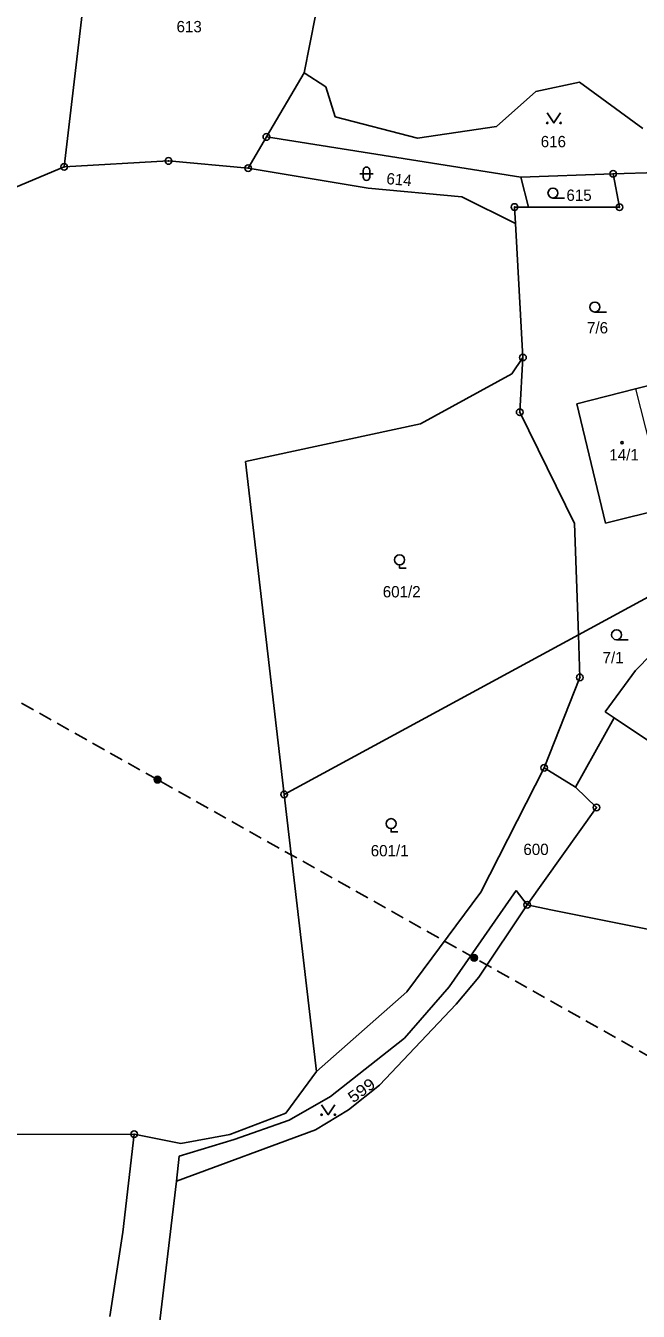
# Model space of a CAD drawing. Extents: x -653193 to -651624, y -1092017 to -1090260.
# Drawn here: x -653063.5 to -652971.4, y -1091442.9 to -1091249.7 of the extents above; entities that cross this region are included whole.
import ezdxf
from ezdxf.enums import TextEntityAlignment as Align

# ---------------------------------------------------------------- set-up
doc = ezdxf.new("R2010")
doc.units = 0
doc.header["$LTSCALE"] = 0.68
doc.linetypes.add('MEDIUM_DASHED', pattern=[4.5, 3, -1.5])
for name, color, linetype, lineweight in [('1', 7, 'Continuous', 25), ('3', 7, 'Continuous', 25), ('4', 7, 'Continuous', 13), ('5', 7, 'Continuous', 25), ('6', 7, 'Continuous', 25), ('8', 7, 'Continuous', 25)]:
    doc.layers.add(name, color=color, linetype=linetype, lineweight=lineweight)
doc.layers.add('2', color=7, linetype='Continuous')

msp = doc.modelspace()

# ---------------------------------------------------------------- linework, layer by layer
at = {"layer": '1'}
for p, q in [((-653052.81, -1091229.31), (-653057.71, -1091270.93)), ((-653019.92, -1091248.19), (-653021.65, -1091256.78)), ((-653021.65, -1091256.78), (-653027.32, -1091266.43)), ((-653021.65, -1091256.78), (-653018.37, -1091258.88)), ((-653018.37, -1091258.88), (-653016.96, -1091263.43)), ((-652986.8, -1091259.58), (-652980.24, -1091258.22)), ((-652980.24, -1091258.22), (-652970.74, -1091265.15)), ((-652992.75, -1091264.88), (-652986.8, -1091259.58)), ((-653016.96, -1091263.43), (-653004.6, -1091266.61)), ((-653004.6, -1091266.61), (-652992.75, -1091264.88)), ((-653027.32, -1091266.43), (-653030.07, -1091271.12)), ((-652989.05, -1091272.45), (-653027.32, -1091266.43)), ((-653057.71, -1091270.93), (-653085.61, -1091282.61)), ((-653042.04, -1091270.04), (-653057.71, -1091270.93)), ((-653030.07, -1091271.12), (-653042.04, -1091270.04)), ((-653012.01, -1091274.15), (-653030.07, -1091271.12)), ((-652975.2, -1091271.97), (-652989.05, -1091272.45)), ((-652989.05, -1091272.45), (-652987.94, -1091276.96)), ((-652975.2, -1091271.97), (-652968.54, -1091271.76)), ((-652975.2, -1091271.97), (-652974.24, -1091276.99)), ((-652997.96, -1091275.44), (-653012.01, -1091274.15)), ((-652989.88, -1091279.42), (-652997.96, -1091275.44)), ((-652989.88, -1091279.42), (-652990.02, -1091276.96)), ((-652990.02, -1091276.96), (-652987.94, -1091276.96)), ((-652974.24, -1091276.99), (-652987.94, -1091276.96)), ((-652989.88, -1091279.42), (-652988.75, -1091299.58)), ((-652988.75, -1091299.58), (-652990.44, -1091302.05)), ((-652988.75, -1091299.58), (-652989.24, -1091307.8)), ((-652990.44, -1091302.05), (-653004.17, -1091309.54)), ((-652963.46, -1091302.17), (-652971.81, -1091304.28)), ((-652980.64, -1091306.55), (-652971.81, -1091304.28)), ((-652976.34, -1091324.46), (-652980.64, -1091306.55)), ((-653004.17, -1091309.54), (-653030.47, -1091315.21)), ((-652989.24, -1091307.8), (-652981.01, -1091324.51)), ((-653030.47, -1091315.21), (-653024.64, -1091365.24)), ((-652967.29, -1091322.23), (-652976.34, -1091324.46)), ((-652981.01, -1091324.51), (-652980.42, -1091341.26)), ((-652964.17, -1091332.45), (-652980.42, -1091341.26)), ((-652956.81, -1091331.27), (-652971.83, -1091346.61)), ((-652980.42, -1091341.26), (-653024.64, -1091365.24)), ((-652980.42, -1091341.26), (-652980.19, -1091347.66)), ((-652980.19, -1091347.66), (-652985.56, -1091361.24)), ((-652971.83, -1091346.61), (-652976.38, -1091352.86)), ((-652980.85, -1091364.16), (-652975.06, -1091353.74)), ((-652975.06, -1091353.74), (-652976.38, -1091352.86)), ((-652958.56, -1091364.74), (-652975.06, -1091353.74)), ((-652995.09, -1091379.94), (-652985.56, -1091361.24)), ((-652985.56, -1091361.24), (-652980.85, -1091364.16)), ((-653024.64, -1091365.24), (-653019.78, -1091406.9)), ((-652980.85, -1091364.16), (-652977.7, -1091367.21)), ((-652977.7, -1091367.21), (-652988.11, -1091381.83)), ((-653006.23, -1091394.93), (-652995.09, -1091379.94)), ((-652989.78, -1091379.7), (-652999.85, -1091394.19)), ((-652988.11, -1091381.83), (-652989.78, -1091379.7)), ((-652995.36, -1091392.72), (-652988.11, -1091381.83)), ((-652988.11, -1091381.83), (-652984.56, -1091382.58)), ((-652984.56, -1091382.58), (-652960.27, -1091387.47)), ((-652998.8, -1091396.75), (-652995.36, -1091392.72)), ((-652999.85, -1091394.19), (-653006.57, -1091401.88)), ((-653019.78, -1091406.9), (-653006.23, -1091394.93)), ((-653010.33, -1091408.94), (-652998.8, -1091396.75)), ((-653006.57, -1091401.88), (-653017.69, -1091410.66)), ((-653024.38, -1091413.15), (-653019.78, -1091406.9)), ((-653014.96, -1091412.65), (-653010.33, -1091408.94)), ((-653017.69, -1091410.66), (-653023.91, -1091414.19)), ((-653032.8, -1091416.34), (-653024.38, -1091413.15)), ((-653019.94, -1091415.64), (-653014.96, -1091412.65)), ((-653040.83, -1091423.38), (-653019.94, -1091415.64)), ((-653023.91, -1091414.19), (-653032.15, -1091417.13)), ((-653091.87, -1091416.43), (-653047.2, -1091416.3)), ((-653048.92, -1091431.03), (-653047.2, -1091416.3)), ((-653047.2, -1091416.3), (-653040.2, -1091417.71)), ((-653032.15, -1091417.13), (-653040.42, -1091419.63)), ((-653040.2, -1091417.71), (-653032.8, -1091416.34)), ((-653040.42, -1091419.63), (-653040.83, -1091423.38)), ((-653044.11, -1091450.65), (-653040.83, -1091423.38)), ((-653050.88, -1091443.73), (-653048.92, -1091431.03))]:
    msp.add_line(p, q, dxfattribs=at)
at = {"layer": '3'}
for p, q in [((-653013.281, -1091271.951), (-653011.279, -1091271.951)), ((-653012.781, -1091271.451), (-653012.781, -1091272.452)), ((-653011.779, -1091272.452), (-653011.779, -1091271.451)), ((-652984.243, -1091275.61), (-652982.493, -1091275.61)), ((-652977.943, -1091292.74), (-652976.193, -1091292.74)), ((-652974.673, -1091342), (-652972.923, -1091342))]:
    msp.add_line(p, q, dxfattribs=at)
for points in [[(-652985.09, -1091262.829), (-652984.09, -1091264.33), (-652983.09, -1091262.829)], [(-653007.3, -1091330.742), (-653007.3, -1091331.24), (-653006.299, -1091331.24)], [(-653008.57, -1091370.392), (-653008.57, -1091370.89), (-653007.569, -1091370.89)], [(-653019.02, -1091411.899), (-653018.02, -1091413.4), (-653017.02, -1091411.899)]]:
    msp.add_lwpolyline(points, dxfattribs=at)
for centre, radius in [((-652985.09, -1091264.3295), 0.1), ((-652983.09, -1091264.3295), 0.1), ((-652984.2429, -1091274.8598), 0.75), ((-652977.9429, -1091291.9898), 0.75), ((-653007.2993, -1091329.9909), 0.75), ((-652974.6729, -1091341.2498), 0.75), ((-653008.5693, -1091369.6409), 0.75), ((-653019.02, -1091413.3995), 0.1), ((-653017.02, -1091413.3995), 0.1)]:
    msp.add_circle(centre, radius, dxfattribs=at)
for centre, start, end in [((-653012.28, -1091271.4509), 0, 180), ((-653012.28, -1091272.4509), 180, 359.98789)]:
    msp.add_arc(centre, 0.5, start, end, dxfattribs=at)
at = {"layer": '4'}
msp.add_line((-652971.81, -1091304.28), (-652967.29, -1091322.23), dxfattribs=at)
at = {"layer": '5'}
msp.add_circle((-652973.8368, -1091312.3792), 0.175, dxfattribs=at)
at = {"layer": '6', "linetype": 'MEDIUM_DASHED'}
for p, q in [((-653043.67, -1091363.03), (-653091.4, -1091336.17)), ((-652996.08, -1091389.81), (-653043.67, -1091363.03)), ((-652945.51, -1091418.3), (-652996.08, -1091389.81))]:
    msp.add_line(p, q, dxfattribs=at)
at = {"layer": '6'}
for centre, radius in [((-653043.6734, -1091363.0299), 0.5), ((-653043.6734, -1091363.0299), 0.4), ((-653043.6734, -1091363.0299), 0.3), ((-653043.6734, -1091363.0299), 0.2), ((-653043.6734, -1091363.0299), 0.1), ((-652996.0834, -1091389.8099), 0.5), ((-652996.0834, -1091389.8099), 0.4), ((-652996.0834, -1091389.8099), 0.3), ((-652996.0834, -1091389.8099), 0.2), ((-652996.0834, -1091389.8099), 0.1)]:
    msp.add_circle(centre, radius, dxfattribs=at)
at = {"layer": '8'}
for centre, radius in [((-653027.32, -1091266.4299), 0.5), ((-653027.32, -1091266.4299), 0.0303), ((-653057.71, -1091270.9299), 0.5), ((-653057.71, -1091270.9299), 0.0303), ((-653042.04, -1091270.0399), 0.5), ((-653042.04, -1091270.0399), 0.0303), ((-653030.07, -1091271.1199), 0.5), ((-653030.07, -1091271.1199), 0.0303), ((-652975.2, -1091271.9699), 0.5), ((-652975.2, -1091271.9699), 0.0303), ((-652990.02, -1091276.9599), 0.5), ((-652974.24, -1091276.9899), 0.5), ((-652990.02, -1091276.9599), 0.0303), ((-652974.24, -1091276.9899), 0.0303), ((-652988.75, -1091299.5799), 0.5), ((-652988.75, -1091299.5799), 0.0303), ((-652989.24, -1091307.7999), 0.5), ((-652989.24, -1091307.7999), 0.0303), ((-652980.19, -1091347.6599), 0.5), ((-652980.19, -1091347.6599), 0.0303), ((-652985.56, -1091361.2399), 0.5), ((-652985.56, -1091361.2399), 0.0303), ((-653024.64, -1091365.2399), 0.5), ((-653024.64, -1091365.2399), 0.0303), ((-652977.7, -1091367.2099), 0.5), ((-652977.7, -1091367.2099), 0.0303), ((-652988.11, -1091381.8299), 0.5), ((-652988.11, -1091381.8299), 0.0303), ((-653047.2, -1091416.2999), 0.5), ((-653047.2, -1091416.2999), 0.0303)]:
    msp.add_circle(centre, radius, dxfattribs=at)

# ---------------------------------------------------------------- texts
at = {"layer": '2'}
for s, p in [('613', (-653038.929, -1091250.695)), ('616', (-652984.179, -1091267.975)), ('615', (-652980.319, -1091276.035)), ('7/6', (-652977.54, -1091295.955)), ('14/1', (-652973.549, -1091315.055)), ('601/2', (-653006.98, -1091335.635)), ('7/1', (-652975.2, -1091345.535)), ('601/1', (-653008.79, -1091374.555)), ('600', (-652986.789, -1091374.355))]:
    msp.add_text(s, height=1.7, dxfattribs=at).set_placement(p, align=Align.CENTER)
msp.add_text('614', height=1.7, rotation=355, dxfattribs=at).set_placement((-653007.4386, -1091273.6761), align=Align.CENTER)
at = {"layer": '2', "width": 1.15}
msp.add_text('599', height=1.7, rotation=36, dxfattribs=at).set_placement((-653012.5246, -1091410.4186), align=Align.CENTER)

doc.saveas('drawing.dxf')
